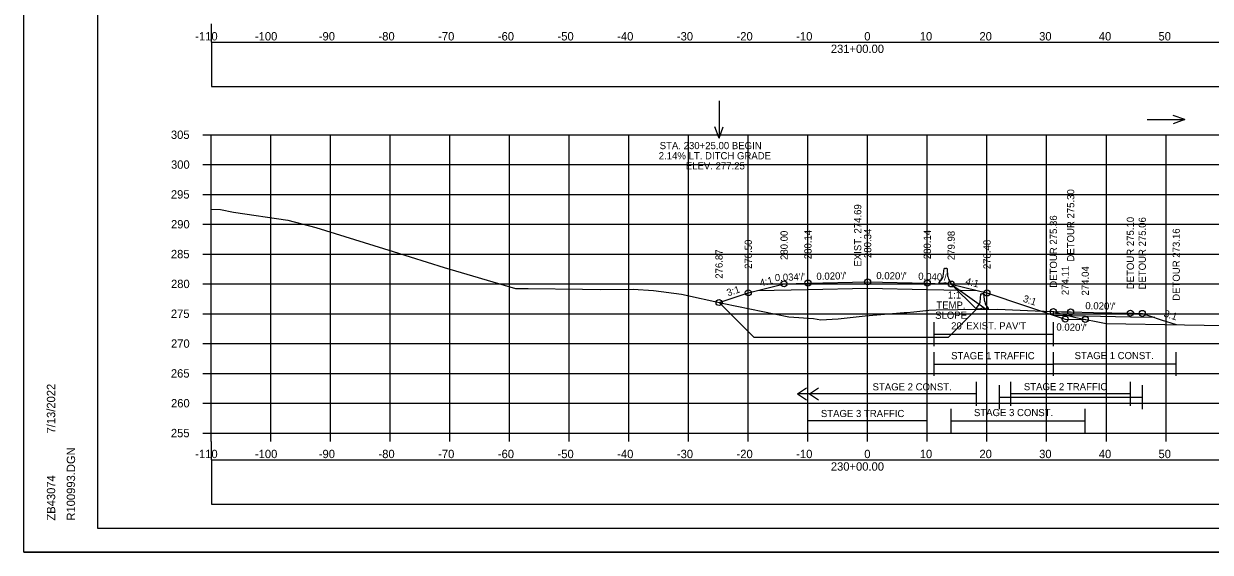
# Model space of a CAD drawing. Extents: x 4667 to 1632277, y -2100 to 724501.
# Drawn here: x 5635.8 to 5834.6, y 596.3 to 684.9 of the extents above; entities that cross this region are included whole.
import ezdxf

# ---------------------------------------------------------------- set-up
doc = ezdxf.new("R2010")
doc.units = 0
for name, color, linetype in [('R_Alt Surface', 7, 'Continuous'), ('R_Axis', 7, 'Continuous'), ('R_Axis Annot', 7, 'Continuous'), ('R_Border', 7, 'Continuous'), ('R_Border Notes', 7, 'Continuous'), ('R_Detour', 7, 'Continuous'), ('R_Detour Annot', 7, 'Continuous'), ('R_Exist Surface', 7, 'Continuous'), ('R_Fin Surface', 7, 'Continuous'), ('R_Fin Surface Annot', 7, 'Continuous'), ('R_Grid', 7, 'Continuous'), ('R_MOT', 7, 'Continuous'), ('R_No Plot', 7, 'Continuous'), ('R_Proposed CofA', 7, 'Continuous'), ('R_ROW', 7, 'Continuous'), ('R_Temp Easement', 7, 'Continuous'), ('R_Water Annot', 7, 'Continuous'), ('T_Drafting', 7, 'Continuous')]:
    doc.layers.add(name, color=color, linetype=linetype)

msp = doc.modelspace()

# ---------------------------------------------------------------- linework, layer by layer
at = {"layer": 'R_Alt Surface'}
msp.add_lwpolyline([(5758.73, 640.16), (5767.18, 640.33), (5777.18, 640.53), (5787.18, 640.33), (5795.55, 640.16)], dxfattribs=at)
at = {"layer": 'R_Axis'}
for p, q in [((5665.78, 666.27), (5667.18, 666.27)), ((5667.18, 616.27), (5667.18, 666.27)), ((5665.78, 661.27), (5667.18, 661.27)), ((5665.78, 656.27), (5667.18, 656.27)), ((5665.78, 651.27), (5667.18, 651.27)), ((5665.78, 646.27), (5667.18, 646.27)), ((5665.78, 641.27), (5667.18, 641.27)), ((5665.78, 636.27), (5667.18, 636.27)), ((5665.78, 631.27), (5667.18, 631.27)), ((5665.78, 626.27), (5667.18, 626.27)), ((5665.78, 621.27), (5667.18, 621.27)), ((5665.78, 616.27), (5667.18, 616.27)), ((5667.18, 616.27), (5947.18, 616.27)), ((5667.18, 614.87), (5667.18, 616.27)), ((5677.18, 614.87), (5677.18, 616.27)), ((5687.18, 614.87), (5687.18, 616.27)), ((5697.18, 614.87), (5697.18, 616.27)), ((5707.18, 614.87), (5707.18, 616.27)), ((5717.18, 614.87), (5717.18, 616.27)), ((5727.18, 614.87), (5727.18, 616.27)), ((5737.18, 614.87), (5737.18, 616.27)), ((5747.18, 614.87), (5747.18, 616.27)), ((5757.18, 614.87), (5757.18, 616.27)), ((5767.18, 614.87), (5767.18, 616.27)), ((5777.18, 614.87), (5777.18, 616.27)), ((5787.18, 614.87), (5787.18, 616.27)), ((5797.18, 614.87), (5797.18, 616.27)), ((5807.18, 614.87), (5807.18, 616.27)), ((5817.18, 614.87), (5817.18, 616.27)), ((5827.18, 614.87), (5827.18, 616.27))]:
    msp.add_line(p, q, dxfattribs=at)
at = {"layer": 'R_Border'}
for p, q in [((5648.18, 600.27), (5648.18, 805.73)), ((5648.18, 600.27), (5648.18, 600.27)), ((5964.36, 600.27), (5648.18, 600.27))]:
    msp.add_line(p, q, dxfattribs=at)
at = {"layer": 'R_Detour'}
for points in [[(5825.33, 635.62), (5821.2, 635.71), (5811.2, 635.91), (5808.31, 635.97), (5808.31, 636.63)], [(5808.31, 636.63), (5809.65, 636.6), (5811.2, 636.57), (5815.01, 636.5), (5821.2, 636.37), (5821.96, 636.36), (5823.2, 636.33), (5824.42, 635.93), (5826.39, 635.27), (5828.89, 634.44)]]:
    msp.add_lwpolyline(points, dxfattribs=at)
at = {"layer": 'R_Exist Surface'}
msp.add_lwpolyline([(5667.18, 653.8), (5668.73, 653.72), (5670.9, 653.3), (5680.03, 651.96), (5684.7, 650.7), (5697.68, 646.69), (5706.25, 644), (5718.19, 640.52), (5719.52, 640.49), (5720.28, 640.49), (5729.38, 640.36), (5732.47, 640.33), (5737.87, 640.38), (5741.3, 640.16), (5745.98, 639.56), (5753.06, 637.97), (5763.98, 635.73), (5768.11, 635.48), (5769.34, 635.27), (5771.26, 635.37), (5772.25, 635.4), (5776.78, 635.93), (5783.31, 636.46), (5783.77, 636.49), (5784.93, 636.58), (5787.41, 636.85), (5788.66, 636.94), (5792.29, 636.98), (5798.95, 637.05), (5805.25, 636.75), (5808.31, 636.63), (5809.21, 636.34), (5809.9, 636.2), (5812.05, 635.62), (5817.13, 634.66), (5843.4, 634.16)], dxfattribs=at)
at = {"layer": 'R_Fin Surface'}
msp.add_lwpolyline([(5752.28, 638.14), (5757.18, 639.78), (5758.73, 640.16), (5763.18, 641.28), (5767.18, 641.41), (5777.18, 641.61), (5787.18, 641.41), (5791.18, 641.25), (5795.55, 640.16), (5797.18, 639.75), (5810.29, 635.38), (5813.65, 635.32)], dxfattribs=at)
at = {"layer": 'R_Grid'}
for p, q in [((5667.18, 666.27), (5947.18, 666.27)), ((5667.18, 616.27), (5667.18, 666.27)), ((5677.18, 616.27), (5677.18, 666.27)), ((5687.18, 616.27), (5687.18, 666.27)), ((5697.18, 616.27), (5697.18, 666.27)), ((5707.18, 616.27), (5707.18, 666.27)), ((5717.18, 616.27), (5717.18, 666.27)), ((5727.18, 616.27), (5727.18, 666.27)), ((5737.18, 616.27), (5737.18, 666.27)), ((5747.18, 616.27), (5747.18, 666.27)), ((5757.18, 616.27), (5757.18, 666.27)), ((5767.18, 616.27), (5767.18, 666.27)), ((5777.18, 616.27), (5777.18, 666.27)), ((5787.18, 616.27), (5787.18, 666.27)), ((5797.18, 616.27), (5797.18, 666.27)), ((5807.18, 616.27), (5807.18, 666.27)), ((5817.18, 616.27), (5817.18, 666.27)), ((5827.18, 616.27), (5827.18, 666.27)), ((5667.18, 661.27), (5947.18, 661.27)), ((5667.18, 656.27), (5947.18, 656.27)), ((5667.18, 651.27), (5947.18, 651.27)), ((5667.18, 646.27), (5947.18, 646.27)), ((5667.18, 641.27), (5947.18, 641.27)), ((5667.18, 636.27), (5947.18, 636.27)), ((5667.18, 631.27), (5947.18, 631.27)), ((5667.18, 626.27), (5947.18, 626.27)), ((5667.18, 621.27), (5947.18, 621.27)), ((5667.18, 616.27), (5947.18, 616.27))]:
    msp.add_line(p, q, dxfattribs=at)
at = {"layer": 'R_MOT'}
for p, q in [((5789.84, 642.52), (5790.03, 643.83)), ((5790.09, 643.88), (5790.29, 643.87)), ((5790.48, 643.87), (5790.29, 643.87)), ((5790.63, 642.49), (5790.54, 643.81)), ((5789.19, 641.5), (5789.68, 642.14)), ((5789.19, 641.33), (5789.19, 641.5)), ((5789.69, 641.31), (5789.19, 641.33)), ((5790.19, 641.46), (5789.69, 641.31)), ((5790.68, 641.27), (5790.19, 641.46)), ((5791.18, 641.25), (5790.68, 641.27)), ((5791.19, 641.42), (5790.76, 642.09)), ((5791.18, 641.25), (5791.19, 641.42)), ((5796.02, 638.23), (5796.14, 639.55)), ((5796.2, 639.61), (5796.39, 639.61)), ((5796.58, 639.61), (5796.39, 639.61)), ((5796.8, 638.24), (5796.65, 639.56)), ((5795.42, 637.18), (5795.87, 637.84)), ((5795.43, 637.01), (5795.42, 637.18)), ((5795.93, 637.02), (5795.43, 637.01)), ((5796.42, 637.19), (5795.93, 637.02)), ((5796.93, 637.03), (5796.42, 637.19)), ((5797.43, 637.04), (5796.93, 637.03)), ((5797.42, 637.21), (5796.95, 637.86)), ((5797.43, 637.04), (5797.42, 637.21))]:
    msp.add_line(p, q, dxfattribs=at)
for centre, radius, start, end in [((5789.02, 642.64), 0.833, 322.7174, 351.7004), ((5790.09, 643.82), 0.0625, 87.7094, 171.7004), ((5790.48, 643.8), 0.0625, 3.7184, 87.7094), ((5791.46, 642.54), 0.833, 183.7184, 212.7014), ((5795.19, 638.31), 0.833, 325.7832, 354.7662), ((5796.2, 639.54), 0.0625, 90.7752, 174.7662), ((5796.59, 639.55), 0.0625, 6.7842, 90.7752), ((5797.63, 638.34), 0.833, 186.7842, 215.7672)]:
    msp.add_arc(centre, radius, start, end, dxfattribs=at)
at = {"layer": 'R_No Plot'}
for p, q in [((5667.18, 684.87), (5667.18, 681.8)), ((5791.18, 641.25), (5797.05, 637.03)), ((5799.2, 624.27), (5799.2, 620.27)), ((5823.2, 624.27), (5823.2, 620.27)), ((5799.2, 622.27), (5823.2, 622.27)), ((5667.18, 614.87), (5667.18, 611.8)), ((5635.78, 596.29), (5969.12, 596.29))]:
    msp.add_line(p, q, dxfattribs=at)
for points in [[(5635.78, 809.63), (5969.12, 809.63), (5969.12, 596.29), (5635.78, 596.29)], [(5882.1, 805.73), (5901.72, 805.73), (5901.72, 795.85), (5917.84, 795.85), (5941.04, 795.85), (5941.04, 771.52), (5964.36, 771.52), (5964.36, 600.27), (5648.18, 600.27), (5648.18, 805.73)]]:
    msp.add_lwpolyline(points, close=True, dxfattribs=at)
for centre in [(5757.18, 639.78), (5763.18, 641.28), (5767.18, 641.41), (5777.18, 641.61), (5787.18, 641.41), (5791.18, 641.25), (5797.18, 639.75), (5752.28, 638.14), (5808.31, 636.63), (5811.2, 636.57), (5821.2, 636.37), (5823.2, 636.33), (5810.29, 635.38), (5813.65, 635.32)]:
    msp.add_circle(centre, 0.5, dxfattribs=at)
at = {"layer": 'R_Proposed CofA'}
for p, q in [((5765.43, 622.84), (5766.93, 623.84)), ((5765.43, 622.84), (5766.93, 621.84)), ((5767.43, 622.84), (5768.93, 623.84)), ((5767.43, 622.84), (5768.93, 621.84))]:
    msp.add_line(p, q, dxfattribs=at)
for points in [[(5667.23, 674.33), (5947.13, 674.33), (5947.13, 681.75), (5667.23, 681.75)], [(5667.23, 604.33), (5947.13, 604.33), (5947.13, 611.75), (5667.23, 611.75)]]:
    msp.add_lwpolyline(points, close=True, dxfattribs=at)
at = {"layer": 'R_ROW'}
for p, q in [((5752.28, 638.14), (5758.15, 632.27)), ((5795.43, 637.01), (5790.69, 632.27)), ((5790.69, 632.27), (5758.15, 632.27))]:
    msp.add_line(p, q, dxfattribs=at)
at = {"layer": 'R_Temp Easement'}
for p, q in [((5788.31, 630.84), (5788.31, 634.84)), ((5808.31, 630.84), (5808.31, 634.84)), ((5788.31, 632.84), (5808.31, 632.84)), ((5788.31, 625.84), (5788.31, 629.84)), ((5808.31, 625.84), (5808.31, 629.84)), ((5828.89, 625.84), (5828.89, 629.84)), ((5788.31, 627.84), (5808.31, 627.84)), ((5828.89, 627.84), (5808.3, 627.84)), ((5795.43, 620.84), (5795.43, 624.84)), ((5801.2, 620.84), (5801.2, 624.84)), ((5821.2, 620.84), (5821.2, 624.84)), ((5795.43, 622.84), (5765.43, 622.84)), ((5821.2, 622.84), (5801.2, 622.84)), ((5767.18, 616.34), (5767.18, 620.34)), ((5787.18, 616.34), (5787.18, 620.34)), ((5791.18, 616.34), (5791.18, 620.34)), ((5813.65, 616.34), (5813.65, 620.34)), ((5787.18, 618.34), (5767.18, 618.34)), ((5791.18, 618.34), (5813.65, 618.34))]:
    msp.add_line(p, q, dxfattribs=at)
at = {"layer": 'R_Water Annot'}
for p, q in [((5752.28, 671.96), (5752.28, 665.67)), ((5824.04, 668.82), (5830.33, 668.82)), ((5830.33, 668.82), (5828.4, 669.52)), ((5830.33, 668.82), (5828.4, 668.12)), ((5752.28, 665.67), (5751.58, 667.6)), ((5752.28, 665.67), (5752.98, 667.6))]:
    msp.add_line(p, q, dxfattribs=at)
at = {"layer": 'T_Drafting'}
msp.add_line((5791.18, 641.25), (5795.43, 637.01), dxfattribs=at)

# ---------------------------------------------------------------- texts
at = {"layer": 'R_Axis Annot'}
for s, p in [('-110', (5664.52, 682.07)), ('-100', (5674.52, 682.07)), ('-90', (5685.22, 682.07)), ('-80', (5695.22, 682.07)), ('-70', (5705.22, 682.07)), ('-60', (5715.22, 682.07)), ('-50', (5725.22, 682.07)), ('-40', (5735.22, 682.07)), ('-30', (5745.22, 682.07)), ('-20', (5755.22, 682.07)), ('-10', (5765.22, 682.07)), ('0', (5776.62, 682.07)), ('10', (5785.92, 682.07)), ('20', (5795.92, 682.07)), ('30', (5805.92, 682.07)), ('40', (5815.92, 682.07)), ('50', (5825.92, 682.07)), ('231+00.00', (5771.02, 679.97)), ('305', (5660.44, 665.57)), ('300', (5660.46, 660.57)), ('295', (5660.44, 655.57)), ('290', (5660.46, 650.57)), ('285', (5660.44, 645.57)), ('280', (5660.46, 640.57)), ('275', (5660.44, 635.57)), ('270', (5660.46, 630.57)), ('265', (5660.44, 625.57)), ('260', (5660.46, 620.57)), ('255', (5660.44, 615.57)), ('-110', (5664.52, 612.07)), ('-100', (5674.52, 612.07)), ('-90', (5685.22, 612.07)), ('-80', (5695.22, 612.07)), ('-70', (5705.22, 612.07)), ('-60', (5715.22, 612.07)), ('-50', (5725.22, 612.07)), ('-40', (5735.22, 612.07)), ('-30', (5745.22, 612.07)), ('-20', (5755.22, 612.07)), ('-10', (5765.22, 612.07)), ('0', (5776.62, 612.07)), ('10', (5785.92, 612.07)), ('20', (5795.92, 612.07)), ('30', (5805.92, 612.07)), ('40', (5815.92, 612.07)), ('50', (5825.92, 612.07)), ('230+00.00', (5771.02, 609.97))]:
    msp.add_text(s, height=1.4, dxfattribs=at).set_placement(p)
at = {"layer": 'R_Border'}
for s, p in [('7/13/2022', (5641.05, 616.2)), ('R100993.DGN', (5644.38, 601.6)), ('ZB43074', (5641.05, 601.6))]:
    msp.add_text(s, height=1.4, rotation=90, dxfattribs=at).set_placement(p)
at = {"layer": 'R_Border Notes'}
for s, p in [('TEMP.', (5788.69, 637.12)), ('1:1', (5790.63, 638.82)), ('SLOPE', (5788.49, 635.42))]:
    msp.add_text(s, height=1.2, dxfattribs=at).set_placement(p)
at = {"layer": 'R_Detour Annot'}
for s, rotation, p in [('DETOUR 273.16', 90, (5829.49, 638.44)), ("0.020'/'", 358.8542, (5813.65, 637.03)), ('3:1', 342.6833, (5826.71, 635.81))]:
    msp.add_text(s, height=1.2, rotation=rotation, dxfattribs=at).set_placement(p)
at = {"layer": 'R_Fin Surface Annot'}
for s, rotation, p in [('DETOUR 275.30', 90, (5811.8, 645.01)), ('DETOUR 275.36', 90, (5808.91, 640.63)), ('DETOUR 275.10', 90, (5821.8, 640.37)), ('DETOUR 275.06', 90, (5823.8, 640.33)), ('280.14', 90, (5767.78, 645.41)), ('280.34', 90, (5777.78, 645.61)), ('280.14', 90, (5787.78, 645.41)), ('278.50', 90, (5757.78, 643.78)), ('280.00', 90, (5763.78, 645.28)), ('279.98', 90, (5791.78, 645.25)), ('278.48', 90, (5797.78, 643.75)), ('276.87', 90, (5752.88, 642.14)), ('274.11', 90, (5810.89, 639.38)), ('274.04', 90, (5814.25, 639.32)), ('4:1', 14.0362, (5759.26, 640.81)), ("0.034'/'", 1.9754, (5761.65, 641.72)), ("0.020'/'", 1.1458, (5768.61, 641.94)), ("0.020'/'", 358.8542, (5778.63, 642.08)), ("0.040'/'", 357.7094, (5785.64, 641.98)), ('4:1', 345.9638, (5793.5, 641.19)), ('3:1', 18.4349, (5753.79, 639.17)), ('3:1', 341.5651, (5803.11, 638.31)), ("0.020'/'", 358.8542, (5808.8, 633.46))]:
    msp.add_text(s, height=1.2, rotation=rotation, dxfattribs=at).set_placement(p)
at = {"layer": 'R_Temp Easement'}
msp.add_text('EXIST. 274.69', height=1.2, rotation=90, dxfattribs=at).set_placement((5776.12, 644.18))
for s, height, p in [("20' EXIST. PAV'T", 1.2, (5791.17, 633.64)), ('STAGE 1 TRAFFIC', 1.2, (5791.17, 628.64)), ('STAGE 1 CONST.', 1.1985, (5811.86, 628.66)), ('STAGE 2 CONST.', 1.1985, (5778.01, 623.42)), ('STAGE 2 TRAFFIC', 1.1985, (5803.36, 623.45)), ('STAGE 3 CONST.', 1.1985, (5795, 619.11)), ('STAGE 3 TRAFFIC', 1.1985, (5769.35, 618.95))]:
    msp.add_text(s, height=height, dxfattribs=at).set_placement(p)
at = {"layer": 'R_Water Annot'}
for s, p in [('STA. 230+25.00 BEGIN', (5742.34, 663.85)), ('2.14% LT. DITCH GRADE', (5742.18, 662.15)), ('ELEV. 277.25', (5746.71, 660.45))]:
    msp.add_text(s, height=1.2, dxfattribs=at).set_placement(p)

doc.saveas('drawing.dxf')
